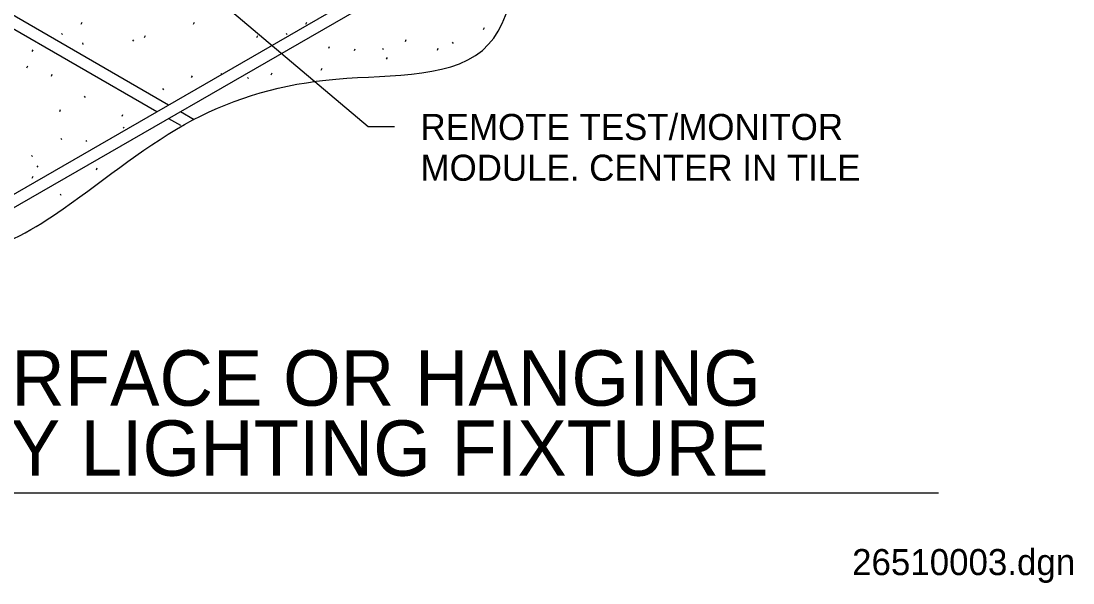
# Model space of a CAD drawing. Extents: x -12092.5 to -12048.3, y -12283.2 to -12205.8.
# Drawn here: x -12075.14 to -12048.26, y -12283.15 to -12268.79 of the extents above; entities that cross this region are included whole.
import ezdxf

# ---------------------------------------------------------------- set-up
doc = ezdxf.new("R2010")
doc.units = 0
for name, color, linetype in [('G-ANNO-TEXT', 7, 'Continuous'), ('G-DETL-LINE', 7, 'Continuous'), ('G-DETL-PATT', 7, 'Continuous')]:
    doc.layers.add(name, color=color, linetype=linetype)

msp = doc.modelspace()

# ---------------------------------------------------------------- linework, layer by layer
at = {"layer": 'G-ANNO-TEXT'}
for p, q in [((-12066.267, -12271.495), (-12071.212, -12267.32)), ((-12065.6, -12271.495), (-12066.267, -12271.495)), ((-12090.219, -12280.845), (-12051.694, -12280.845))]:
    msp.add_line(p, q, dxfattribs=at)
at = {"layer": 'G-DETL-LINE'}
for p, q in [((-12054.535, -12261.21), (-12077.813, -12274.649)), ((-12054.64, -12261.617), (-12077.25, -12274.671)), ((-12078.766, -12266.658), (-12071.369, -12270.929)), ((-12079.067, -12266.832), (-12071.669, -12271.102)), ((-12071.369, -12271.276), (-12071.066, -12271.451)), ((-12071.069, -12271.102), (-12070.72, -12271.304))]:
    msp.add_line(p, q, dxfattribs=at)
msp.add_spline([(-12065.21, -12249.313), (-12068.289, -12248.77), (-12071.882, -12249.967), (-12073.511, -12250.976), (-12075.66, -12253.249), (-12078.578, -12254.568), (-12080.241, -12256.622), (-12082.417, -12257.299), (-12085.365, -12259.047), (-12087.392, -12262.054), (-12087.392, -12263.005), (-12085.887, -12270.459), (-12085.273, -12271.196), (-12082.387, -12274.137), (-12077.474, -12274.659), (-12076.368, -12274.659), (-12074.064, -12273.585), (-12070.747, -12271.315), (-12067.093, -12270.272), (-12063.192, -12269.382), (-12061.824, -12266.02), (-12056.45, -12263.782), (-12054.538, -12261.235), (-12060.102, -12255.74), (-12060.918, -12251.902), (-12062.515, -12250.552), (-12064.841, -12249.447), (-12065.182, -12249.321)], degree=3, dxfattribs=at)
at = {"layer": 'G-DETL-PATT'}
for p, q in [((-12073.601, -12268.864), (-12073.58, -12268.815)), ((-12070.732, -12268.864), (-12070.71, -12268.815)), ((-12067.862, -12268.864), (-12067.84, -12268.815)), ((-12074.106, -12269.102), (-12074.084, -12269.134)), ((-12071.984, -12269.206), (-12071.963, -12269.158)), ((-12069.114, -12269.206), (-12069.093, -12269.158)), ((-12068.366, -12269.102), (-12068.344, -12269.134)), ((-12063.323, -12269.001), (-12063.302, -12268.953)), ((-12073.571, -12269.342), (-12073.566, -12269.39)), ((-12072.289, -12269.267), (-12072.268, -12269.3)), ((-12065.321, -12269.308), (-12065.3, -12269.259)), ((-12064.121, -12269.328), (-12064.099, -12269.36)), ((-12074.854, -12269.569), (-12074.832, -12269.52)), ((-12067.277, -12269.482), (-12067.255, -12269.434)), ((-12066.62, -12269.543), (-12066.599, -12269.495)), ((-12065.907, -12269.479), (-12065.886, -12269.512)), ((-12064.501, -12269.529), (-12064.48, -12269.481)), ((-12074.993, -12269.983), (-12074.971, -12269.935)), ((-12065.8, -12269.764), (-12065.779, -12269.716)), ((-12074.363, -12270.195), (-12074.342, -12270.146)), ((-12070.785, -12270.234), (-12070.764, -12270.186)), ((-12070.037, -12270.13), (-12070.022, -12270.152)), ((-12069.353, -12270.227), (-12069.331, -12270.259)), ((-12068.749, -12270.164), (-12068.728, -12270.115)), ((-12067.471, -12270.04), (-12067.449, -12269.991)), ((-12073.526, -12270.711), (-12073.504, -12270.743)), ((-12071.527, -12270.513), (-12071.505, -12270.545)), ((-12074.151, -12271.098), (-12074.13, -12271.05)), ((-12072.56, -12271.222), (-12072.538, -12271.174)), ((-12072.534, -12271.497), (-12072.513, -12271.53)), ((-12074.126, -12271.779), (-12074.104, -12271.812)), ((-12073.488, -12271.838), (-12073.467, -12271.87)), ((-12074.872, -12272.221), (-12074.85, -12272.253)), ((-12074.735, -12272.488), (-12074.714, -12272.52)), ((-12073.215, -12272.59), (-12073.193, -12272.541)), ((-12074.854, -12272.804), (-12074.832, -12272.756)), ((-12074.143, -12273.205), (-12074.122, -12273.238))]:
    msp.add_line(p, q, dxfattribs=at)

# ---------------------------------------------------------------- texts
at = {"layer": 'G-ANNO-TEXT'}
for s, height, p in [('REMOTE TEST/MONITOR', 0.66667, (-12064.933, -12271.828)), ('MODULE. CENTER IN TILE', 0.66667, (-12064.933, -12272.87)), ('TYPICAL SURFACE OR HANGING', 1.41667, (-12086.446, -12278.621)), ('EMERGENCY LIGHTING FIXTURE', 1.41667, (-12086.352, -12280.413)), ('26510003.dgn', 0.66667, (-12053.905, -12282.952))]:
    msp.add_text(s, height=height, dxfattribs=at).set_placement(p)

doc.saveas('drawing.dxf')
